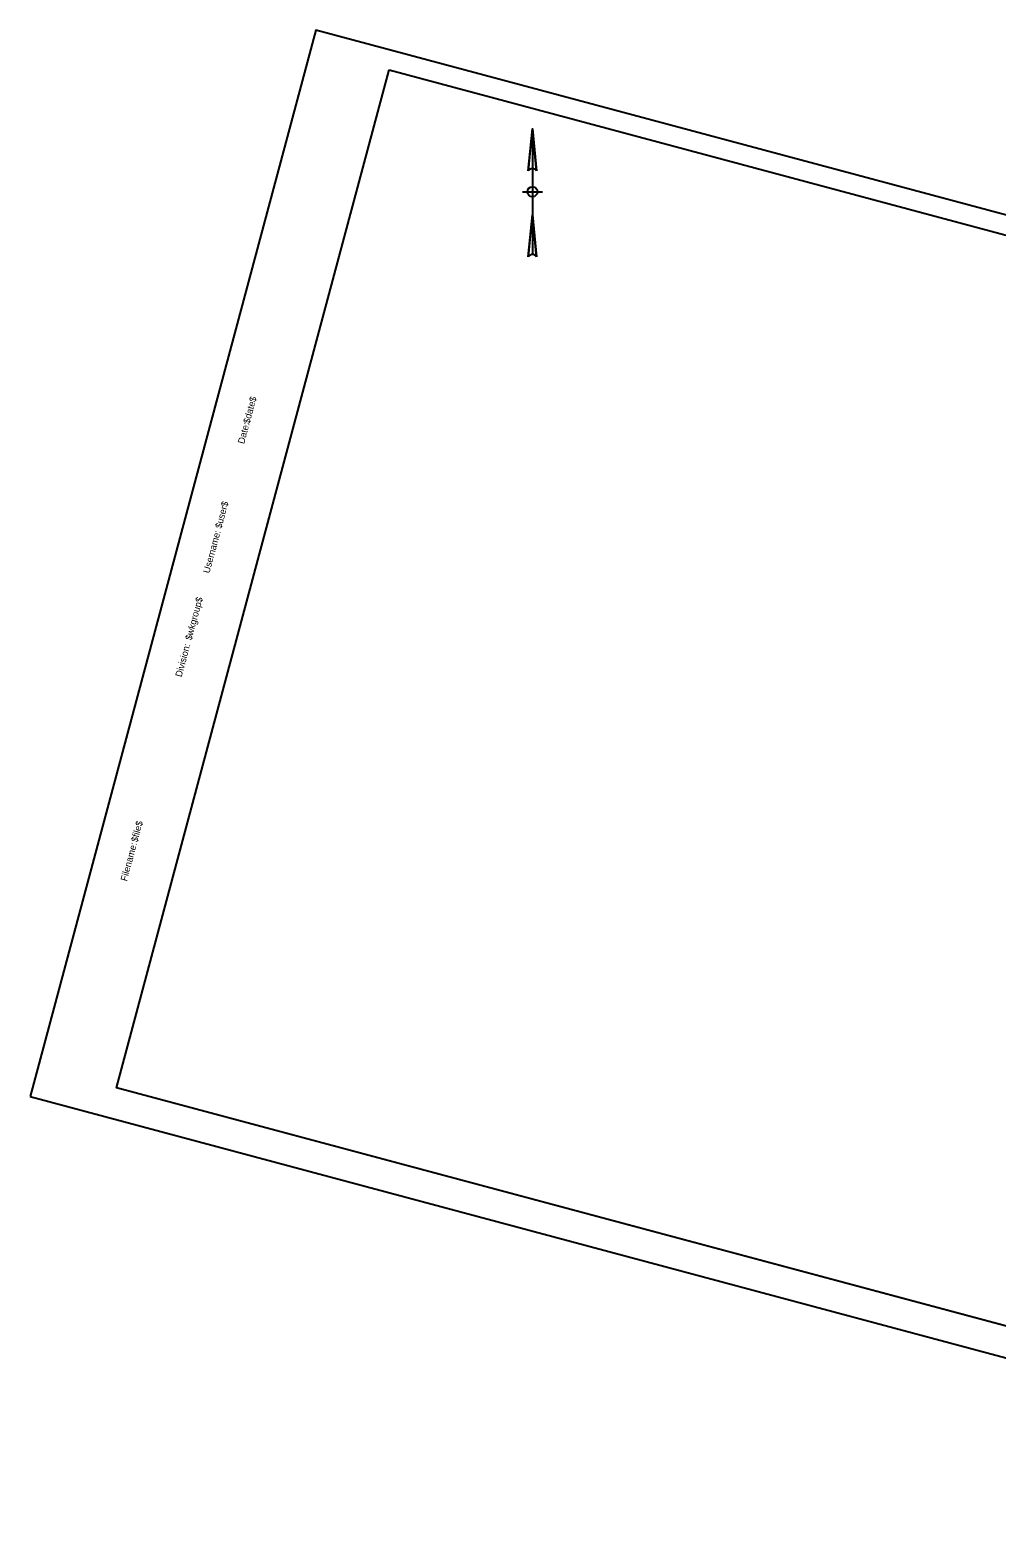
# Model space of a CAD drawing. Extents: x 1764470 to 1765434, y 480207 to 480958.
# Drawn here: x 1764470 to 1764952, y 480207 to 480958 of the extents above; entities that cross this region are included whole.
import ezdxf

# ---------------------------------------------------------------- set-up
doc = ezdxf.new("R2010")
doc.units = 0
for name, color, linetype in [('BORDER', 7, 'Continuous'), ('CLIPS', 7, 'Continuous'), ('H_V CONTROLS', 7, 'Continuous'), ('PLOT BOUNDARY', 7, 'Continuous')]:
    doc.layers.add(name, color=color, linetype=linetype)

msp = doc.modelspace()

# ---------------------------------------------------------------- linework, layer by layer
at = {"layer": 'BORDER'}
msp.add_lwpolyline([(1764649.37, 480938.47), (1765422.11, 480731.41), (1765286.23, 480224.3), (1764513.49, 480431.35)], close=True, dxfattribs=at)
at = {"layer": 'CLIPS'}
msp.add_lwpolyline([(1764649.37, 480938.47), (1765373.82, 480744.35), (1765237.94, 480237.24), (1764513.49, 480431.35)], close=True, dxfattribs=at)
at = {"layer": 'H_V CONTROLS'}
for p, q in [((1764718.63, 480888.23), (1764720.71, 480909.06)), ((1764720.71, 480909.06), (1764720.71, 480846.56)), ((1764720.71, 480909.06), (1764722.8, 480888.23)), ((1764715.71, 480877.81), (1764725.71, 480877.81)), ((1764718.63, 480845.44), (1764720.71, 480866.28)), ((1764720.71, 480866.28), (1764722.8, 480845.44))]:
    msp.add_line(p, q, dxfattribs=at)
for points in [[(1764722.8, 480888.23), (1764720.71, 480909.06), (1764719.67, 480898.65), (1764718.63, 480888.23)], [(1764722.8, 480845.44), (1764720.71, 480866.28), (1764719.67, 480855.86), (1764718.63, 480845.44)]]:
    msp.add_lwpolyline(points, dxfattribs=at)
msp.add_circle((1764720.71, 480877.81), 2.5, dxfattribs=at)
for centre in [(1764720.71, 480886.85), (1764720.71, 480886.85), (1764720.71, 480844.06), (1764720.71, 480844.06)]:
    msp.add_arc(centre, 2.5, 33.55731, 146.44269, dxfattribs=at)
at = {"layer": 'PLOT BOUNDARY'}
msp.add_lwpolyline([(1764470.44, 480427.05), (1765291.48, 480207.06), (1765433.83, 480738.32), (1764612.79, 480958.31)], close=True, dxfattribs=at)

# ---------------------------------------------------------------- texts
at = {"layer": 'BORDER'}
for s, p in [('$date$', (1764579.75, 480762)), ('Date:', (1764577.05, 480751.91)), ('$user$', (1764565.76, 480709.77)), ('Username:', (1764559.77, 480687.44)), ('$wkgroup$', (1764550.85, 480654.12)), ('Division:', (1764545.92, 480635.76)), ('$file$', (1764523.87, 480553.46)), ('Filename:', (1764518.66, 480534.01))]:
    msp.add_text(s, height=3.348, rotation=75, dxfattribs=at).set_placement(p)

doc.saveas('drawing.dxf')
